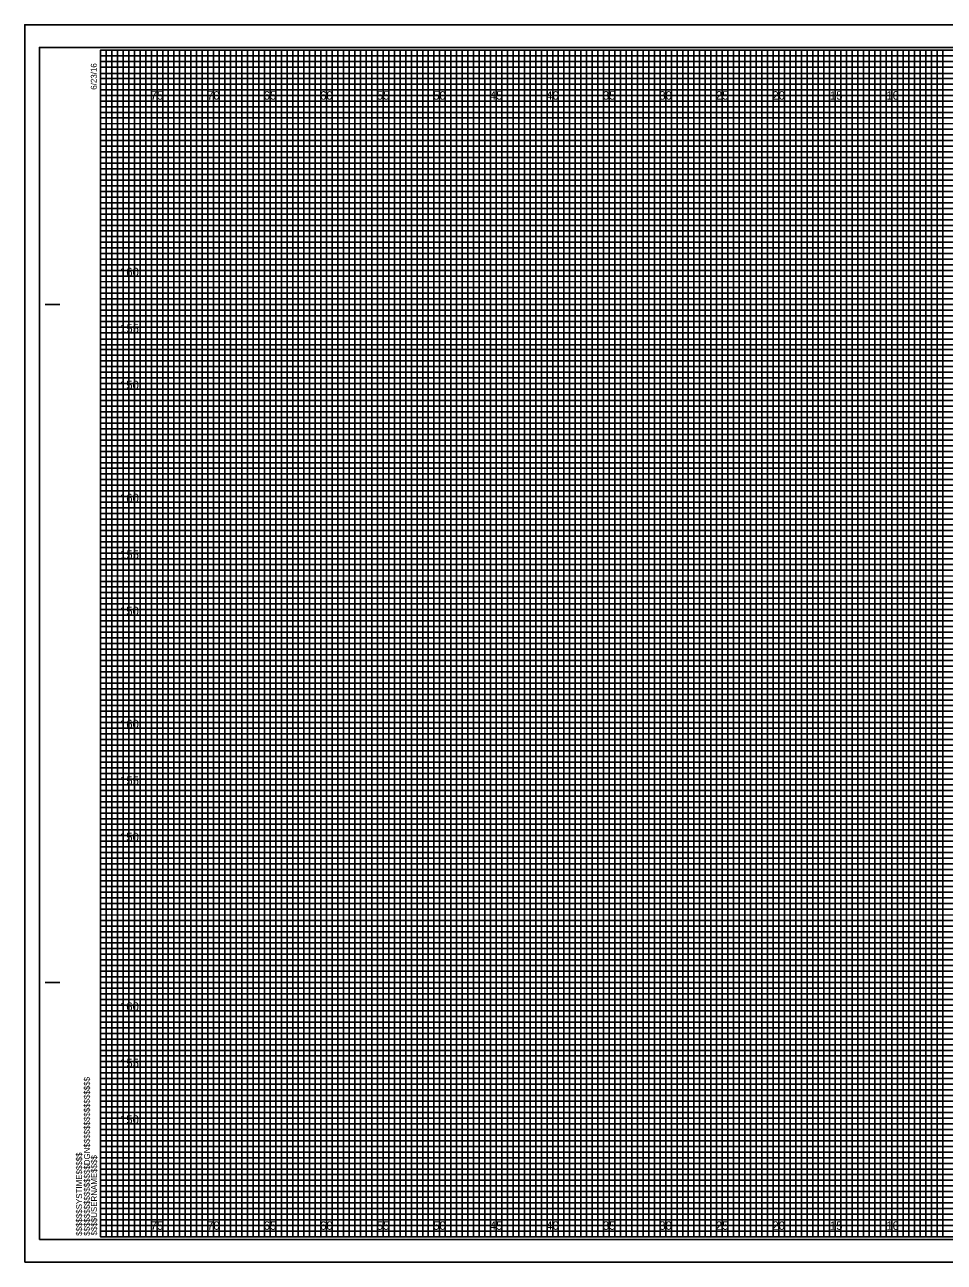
# Model space of a CAD drawing. Extents: x -7 to 162, y 108 to 217.
# Drawn here: x -6.7 to 74.6, y 107.7 to 217.2 of the extents above; entities that cross this region are included whole.
import ezdxf

# ---------------------------------------------------------------- set-up
doc = ezdxf.new("R2010")
doc.units = 0
for name, color, linetype in [('Prop CMT Shear Line', 7, 'Continuous'), ('Prop XS Earthwork Shape', 7, 'Continuous'), ('Prop XS Elevation Labels', 7, 'Continuous'), ('Scratch_Level_1', 7, 'Continuous'), ('Sheet Cross Section CELL', 7, 'Continuous'), ('Sheet Cross Section Grid Minor 1 CELL', 7, 'Continuous'), ('Sheet Cross Section Grid Minor 2 CELL', 7, 'Continuous'), ('Sheet Cutting Line CELL', 7, 'Continuous'), ('Sheet DOT Grid CELL', 7, 'Continuous'), ('Sheet Plot Border Inside CELL', 7, 'Continuous'), ('Sheet Plot Border Outside CELL', 7, 'Continuous')]:
    doc.layers.add(name, color=color, linetype=linetype)

msp = doc.modelspace()

# ---------------------------------------------------------------- linework, layer by layer
at = {"layer": 'Prop CMT Shear Line'}
for p, q in [((5, 215), (0, 215)), ((5, 110), (5, 215)), ((15, 215), (10, 215)), ((10, 215), (10, 110)), ((15, 110), (15, 215)), ((25, 215), (20, 215)), ((20, 215), (20, 110)), ((25, 110), (25, 215)), ((35, 215), (30, 215)), ((30, 215), (30, 110)), ((35, 110), (35, 215)), ((45, 215), (40, 215)), ((40, 215), (40, 110)), ((45, 110), (45, 215)), ((55, 215), (50, 215)), ((50, 215), (50, 110)), ((55, 110), (55, 215)), ((65, 215), (60, 215)), ((60, 215), (60, 110)), ((65, 110), (65, 215)), ((75, 215), (70, 215)), ((70, 215), (70, 110)), ((10, 110), (5, 110)), ((20, 110), (15, 110)), ((30, 110), (25, 110)), ((40, 110), (35, 110)), ((50, 110), (45, 110)), ((60, 110), (55, 110)), ((70, 110), (65, 110))]:
    msp.add_line(p, q, dxfattribs=at)
for points in [[(0, 210), (160, 210), (160, 205), (0, 205)], [(0, 200), (160, 200), (160, 195), (0, 195)], [(0, 190), (160, 190), (160, 185), (0, 185)], [(0, 180), (160, 180), (160, 175), (0, 175)], [(0, 170), (160, 170), (160, 165), (0, 165)], [(0, 160), (160, 160), (160, 155), (0, 155)], [(0, 150), (160, 150), (160, 145), (0, 145)], [(0, 140), (160, 140), (160, 135), (0, 135)], [(0, 130), (160, 130), (160, 125), (0, 125)], [(0, 120), (160, 120), (160, 115), (0, 115)]]:
    msp.add_lwpolyline(points, dxfattribs=at)
at = {"layer": 'Prop XS Earthwork Shape'}
for points in [[(0, 215), (2.5, 215), (2.5, 110), (7.5, 110), (7.5, 215), (12.5, 215), (12.5, 110), (17.5, 110), (17.5, 215), (22.5, 215), (22.5, 110), (27.5, 110), (27.5, 215), (32.5, 215), (32.5, 110), (37.5, 110), (37.5, 215), (42.5, 215), (42.5, 110), (47.5, 110), (47.5, 215), (52.5, 215), (52.5, 110), (57.5, 110), (57.5, 215), (62.5, 215), (62.5, 110), (67.5, 110), (67.5, 215), (72.5, 215), (72.5, 110), (77.5, 110)], [(0, 212.5), (137.5, 212.5)], [(0, 202.5), (160, 202.5), (160, 207.5), (0, 207.5)], [(0, 192.5), (160, 192.5), (160, 197.5), (0, 197.5)], [(0, 182.5), (160, 182.5), (160, 187.5), (0, 187.5)], [(0, 172.5), (160, 172.5), (160, 177.5), (0, 177.5)], [(0, 162.5), (160, 162.5), (160, 167.5), (0, 167.5)], [(0, 152.5), (160, 152.5), (160, 157.5), (0, 157.5)], [(0, 142.5), (160, 142.5), (160, 147.5), (0, 147.5)], [(0, 132.5), (160, 132.5), (160, 137.5), (0, 137.5)], [(0, 122.5), (160, 122.5), (160, 127.5), (0, 127.5)], [(0, 112.5), (160, 112.5), (160, 117.5), (0, 117.5)]]:
    msp.add_lwpolyline(points, dxfattribs=at)
at = {"layer": 'Sheet Cross Section CELL'}
for p, q in [((-4.9, 192.5), (-3.65, 192.5)), ((-4.85, 192.5), (-3.6, 192.5)), ((-4.9, 132.5), (-3.65, 132.5)), ((-4.85, 132.5), (-3.6, 132.5)), ((0, 110), (0, 110)), ((0, 110), (0, 110)), ((0, 110), (0, 110)), ((0, 110), (0, 110)), ((0, 110), (0, 110)), ((0, 110), (0, 110)), ((0, 110), (0, 110))]:
    msp.add_line(p, q, dxfattribs=at)
msp.add_lwpolyline([(160, 215), (0, 215), (0, 110), (160, 110)], close=True, dxfattribs=at)
at = {"layer": 'Sheet Cross Section Grid Minor 1 CELL'}
for p, q in [((0, 214.5), (130, 214.5)), ((130, 213.99), (0, 213.99)), ((0, 213.99), (0, 213.5)), ((0, 213.5), (130, 213.5)), ((130, 212.94), (0, 212.94)), ((0, 212.94), (0, 212)), ((0, 212), (160, 212))]:
    msp.add_line(p, q, dxfattribs=at)
for points in [[(0, 211.5), (135, 211.5), (160, 211.5), (160, 211), (0, 211)], [(0, 210.5), (160, 210.5), (160, 209.5), (0, 209.5)], [(0, 209), (160, 209), (160, 208.5), (0, 208.49)], [(0, 208), (160, 208), (160, 207), (0, 207)], [(0, 206.5), (160, 206.5), (160, 206), (0, 206)], [(0, 205.5), (160, 205.5), (160, 204.5), (0, 204.5)], [(0, 204), (160, 204), (160, 203.5), (0, 203.5)], [(0, 203), (160, 203), (160, 202), (0, 202)], [(0, 201.5), (160, 201.5), (160, 201), (0, 201)], [(0, 200.5), (160, 200.5), (160, 199.5), (0, 199.5)], [(0, 199), (160, 199), (160, 198.5), (0, 198.5)], [(0, 198), (160, 198), (160, 196.97), (160, 196.5), (160, 196), (0, 196)], [(0, 197), (160, 197), (160, 196.5), (0, 196.5)], [(0, 195.5), (160, 195.5), (160, 194.5), (0, 194.52)], [(0, 194.52), (160, 194.5), (160, 194), (0, 194)], [(0, 193.5), (160, 193.5), (160, 193), (0, 193)], [(0, 192), (160, 192), (160, 191.5), (0, 191.5)], [(0, 191), (160, 191), (160, 190.5), (0, 190.5)], [(-0.04, 189.44), (160, 189.44), (160, 188.94), (-0.04, 188.94)], [(0, 188.5), (160, 188.5), (160, 188), (0, 188)], [(0, 187), (160, 187), (160, 186.5), (0, 186.5)], [(0, 186), (160, 186), (160, 185.5), (0, 185.5)], [(0, 184.5), (160, 184.5), (160, 184), (0, 184)], [(0, 183.5), (160, 183.5), (160, 183), (0, 183)], [(0, 182), (160, 182), (160, 181.5), (0, 181.5)], [(0, 181), (160, 181), (160, 180.5), (0, 180.5)], [(0, 179.5), (160, 179.5), (160, 178.99), (0, 179)], [(0, 178.5), (160, 178.5), (160, 178), (0, 178)], [(0, 177), (160, 177), (160, 176.5), (0, 176.5)], [(0, 176), (160, 176), (160, 175.5), (0, 175.5)], [(0, 174.5), (160, 174.5), (160, 174), (0, 174)], [(0, 173.5), (160, 173.5), (160, 173), (0, 173)], [(0, 172), (160, 172), (160, 171.5), (0, 171.5)], [(0, 171), (160, 171), (160, 170.5), (0, 170.5)], [(0, 169.5), (160, 169.5), (160, 169), (0, 169)], [(0, 168.5), (160.03, 168.46), (160, 168), (0, 168)], [(0, 167), (160, 167), (160, 166.5), (0, 166.5)], [(0, 166), (160, 166), (160, 165.5), (0, 165.5)], [(0, 164.5), (160, 164.5), (160, 164), (0, 164)], [(0, 163.5), (160, 163.5), (160, 163), (0, 163)], [(0, 162), (160, 162), (160, 161.5), (0, 161.5)], [(0, 161), (160, 161), (160, 160.5), (0, 160.5)], [(0, 159.5), (160, 159.5), (160, 159), (0, 159)], [(0, 158.5), (160, 158.5), (160, 158), (0, 158)], [(0, 157), (160, 157), (160, 156.5), (0, 156.5)], [(0, 156), (160, 156), (160, 155.5), (0, 155.5)], [(0, 154.5), (160, 154.5), (160, 154), (0, 154)], [(0, 153.5), (160, 153.5), (160, 153), (0, 153)], [(0, 152), (160, 152), (160, 151.5), (0, 151.5)], [(0, 151), (160, 151), (160, 150.5), (0, 150.5)], [(0, 149.5), (160, 149.5), (160, 148.99), (0, 149)], [(0, 148.5), (160, 148.5), (160, 148), (0, 148)], [(0, 147), (160, 147), (160, 146.5), (0, 146.5)], [(0, 146), (160, 146), (160, 145.5), (0, 145.5)], [(0, 144.5), (160, 144.5), (160, 144), (0, 144)], [(0, 143.5), (160, 143.5), (160, 143), (0, 143)], [(0, 142), (160, 142), (160, 141.5), (0, 141.5)], [(0, 141), (160, 141), (160, 140.5), (0, 140.5)], [(0, 139.5), (160, 139.5), (160, 139), (0, 139)], [(0, 138.5), (160.03, 138.46), (160, 138), (0, 138)], [(0, 137), (160, 137), (160, 136.5), (0, 136.5)], [(0, 136), (160, 136), (160, 135.5), (0, 135.5)], [(0, 134.5), (160, 134.5), (160, 134), (0, 134)], [(0, 133.5), (160, 133.5), (160, 133), (0, 133)], [(0, 132), (160, 132), (160, 131.5), (0, 131.5)], [(0, 131), (160, 131), (160, 130.5), (0, 130.5)], [(0, 129.5), (160, 129.5), (160, 129), (0, 129)], [(0, 128.5), (160, 128.5), (160, 128), (0, 128)], [(0, 127), (160, 127), (160, 126.5), (0, 126.5)], [(0, 126), (160, 126), (160, 125.5), (0, 125.5)], [(0, 124.5), (160, 124.5), (160, 124), (0, 124)], [(0, 123.5), (160, 123.5), (160, 123), (0, 123)], [(0, 122), (160, 122), (160, 121.5), (0, 121.5)], [(0, 121), (160, 121), (160, 120.5), (0, 120.5)], [(0, 119.5), (160, 119.5), (160, 119), (0, 119)], [(0, 118.5), (160, 118.5), (160, 118), (0, 118)], [(0, 117), (160, 117), (160, 116.5), (0, 116.5)], [(0, 116), (160, 116), (160, 115.5), (0, 115.5)], [(0, 114.5), (160, 114.5), (160, 114), (0, 114)], [(0, 113.5), (160, 113.5), (160, 113), (0, 113)], [(0, 112), (160, 112), (160, 111.5), (0, 111.5)], [(0, 111), (160, 111), (160, 110.5), (0, 110.5)]]:
    msp.add_lwpolyline(points, dxfattribs=at)
at = {"layer": 'Sheet Cross Section Grid Minor 2 CELL'}
for points in [[(0, 110), (0.5, 110), (0.5, 215), (1, 215), (1, 110)], [(1, 110), (1.5, 110), (1.5, 215), (2, 215), (2, 110)], [(2.5, 110), (3, 110), (3, 215), (3.5, 215), (3.5, 110)], [(3.5, 110), (4, 110), (4, 215), (4.5, 215), (4.5, 110)], [(5, 110), (5.5, 110), (5.5, 215), (6, 215), (6, 110)], [(6, 110), (6.5, 110), (6.5, 215), (7, 215), (7, 110)], [(7.5, 110), (8, 110), (8, 215), (8.5, 215), (8.5, 110)], [(8.5, 110), (9, 110), (9, 215), (9.5, 215), (9.5, 110)], [(10, 110), (10.5, 110), (10.5, 215), (11, 215), (11, 110)], [(11, 110), (11.5, 110), (11.5, 215), (12, 215), (12, 110)], [(12.5, 110), (13, 110), (13, 215), (13.5, 215), (13.5, 110)], [(13.5, 110), (14, 110), (14, 215), (14.5, 215), (14.5, 110)], [(15, 110), (15.5, 110), (15.5, 215), (16, 215), (16, 110)], [(16, 110), (16.5, 110), (16.5, 215), (17, 215), (17, 110)], [(17.5, 110), (18, 110), (18, 215), (18.5, 215), (18.5, 110)], [(18.5, 110), (19, 110), (19, 215), (19.5, 215), (19.5, 110)], [(20, 110), (20.5, 110), (20.5, 215), (21, 215), (21, 110)], [(21, 110), (21.5, 110), (21.5, 215), (22, 215), (22, 110)], [(22.5, 110), (23, 110), (23, 215), (23.5, 215), (23.5, 110)], [(23.5, 110), (24, 110), (24, 215), (24.5, 215), (24.5, 110)], [(25, 110), (25.5, 110), (25.5, 215), (26, 215), (26, 110)], [(26, 110), (26.5, 110), (26.5, 215), (27, 215), (27, 110)], [(27.5, 110), (28, 110), (28, 215), (28.5, 215), (28.5, 110)], [(28.5, 110), (29, 110), (29, 215), (29.5, 215), (29.5, 110)], [(30, 110), (30.5, 110), (30.5, 215), (31, 215), (31, 110)], [(31, 110), (31.5, 110), (31.5, 215), (32, 215), (32, 110)], [(32.5, 110), (33, 110), (33, 215), (33.5, 215), (33.5, 110)], [(33.5, 110), (34, 110), (34, 215), (34.5, 215), (34.5, 110)], [(35, 110), (35.5, 110), (35.5, 215), (36, 215), (36, 110)], [(36, 110), (36.5, 110), (36.5, 215), (37, 215), (37, 110)], [(37.5, 110), (38, 110), (38, 215), (38.5, 215), (38.5, 110)], [(38.5, 110), (39, 110), (39, 215), (39.5, 215), (39.5, 110)], [(40, 110), (40.5, 110), (40.5, 215), (41, 215), (41, 110)], [(41, 110), (41.5, 110), (41.5, 215), (42, 215), (42, 110)], [(42.5, 110), (43, 110), (43, 215), (43.5, 215), (43.5, 110)], [(43.5, 110), (44, 110), (44, 215), (44.5, 215), (44.5, 110)], [(45, 110), (45.5, 110), (45.5, 215), (46, 215), (46, 110)], [(46, 110), (46.5, 110), (46.5, 215), (47, 215), (47, 110)], [(47.5, 110), (48, 110), (48, 215), (48.5, 215), (48.5, 110)], [(48.5, 110), (49, 110), (49, 215), (49.5, 215), (49.5, 110)], [(50, 110), (50.5, 110), (50.5, 215), (51, 215), (51, 110)], [(51, 110), (51.5, 110), (51.5, 215), (52, 215), (52, 110)], [(52.5, 110), (53, 110), (53, 215), (53.5, 215), (53.5, 110)], [(53.5, 110), (54, 110), (54, 215), (54.5, 215), (54.5, 110)], [(55, 110), (55.5, 110), (55.5, 215), (56, 215), (56, 110)], [(56, 110), (56.5, 110), (56.5, 215), (57, 215), (57, 110)], [(57.5, 110), (58, 110), (58, 215), (58.5, 215), (58.5, 110)], [(58.5, 110), (59, 110), (59, 215), (59.5, 215), (59.5, 110)], [(60, 110), (60.5, 110), (60.5, 215), (61, 215), (61, 110)], [(61, 110), (61.5, 110), (61.5, 215), (62, 215), (62, 110)], [(62.5, 110), (63, 110), (63, 215), (63.5, 215), (63.5, 110)], [(63.5, 110), (64, 110), (64, 215), (64.5, 215), (64.5, 110)], [(65, 110), (65.5, 110), (65.5, 215), (66, 215), (66, 110)], [(66, 110), (66.5, 110), (66.5, 215), (67, 215), (67, 110)], [(67.5, 110), (68, 110), (68, 215), (68.5, 215), (68.5, 110)], [(68.5, 110), (69, 110), (69, 215), (69.5, 215), (69.5, 110)], [(70, 110), (70.5, 110), (70.5, 215), (71, 215), (71, 110)], [(71, 110), (71.5, 110), (71.5, 215), (72, 215), (72, 110)], [(72.5, 110), (73, 110), (73, 215), (73.5, 215), (73.5, 110)], [(73.5, 110), (74, 110), (74, 215), (74.5, 215), (74.5, 110)]]:
    msp.add_lwpolyline(points, dxfattribs=at)
at = {"layer": 'Sheet Cutting Line CELL'}
for p, q in [((161.65, 217.25), (-6.7, 217.25)), ((-6.7, 217.25), (-6.7, 107.75)), ((-6.7, 107.75), (161.65, 107.75))]:
    msp.add_line(p, q, dxfattribs=at)
at = {"layer": 'Sheet DOT Grid CELL'}
for p, q in [((5, 110), (5, 215)), ((10, 110), (10, 215)), ((15, 110), (15, 215)), ((20, 110), (20, 215)), ((25, 110), (25, 215)), ((30, 110), (30, 215)), ((35, 110), (35, 215)), ((40, 110), (40, 215)), ((45, 110), (45, 215)), ((50, 110), (50, 215)), ((55, 110), (55, 215)), ((60, 110), (60, 215)), ((65, 110), (65, 215)), ((70, 110), (70, 215)), ((0, 210), (160, 210)), ((0, 205), (160, 205)), ((0, 200), (160, 200)), ((0, 195), (160, 195)), ((0, 190), (160, 190)), ((0, 185), (160, 185)), ((0, 180), (160, 180)), ((0, 175), (160, 175)), ((0, 170), (160, 170)), ((0, 165), (160, 165)), ((0, 160), (160, 160)), ((0, 155), (160, 155)), ((0, 150), (160, 150)), ((0, 145), (160, 145)), ((0, 140), (160, 140)), ((0, 135), (160, 135)), ((0, 130), (160, 130)), ((0, 125), (160, 125)), ((0, 120), (160, 120)), ((0, 115), (160, 115))]:
    msp.add_line(p, q, dxfattribs=at)
at = {"layer": 'Sheet Plot Border Inside CELL'}
msp.add_lwpolyline([(-5.4, 109.75), (161.2, 109.75), (161.2, 215.25), (-5.4, 215.25)], close=True, dxfattribs=at)
at = {"layer": 'Sheet Plot Border Outside CELL'}
msp.add_lwpolyline([(-6.7, 107.75), (161.65, 107.75), (161.65, 217.25), (-6.7, 217.25)], close=True, dxfattribs=at)

# ---------------------------------------------------------------- texts
at = {"layer": 'Prop XS Elevation Labels'}
for s, p in [('160', (1.72, 195)), ('155', (1.73, 190)), ('150', (1.72, 185)), ('160', (1.72, 175)), ('155', (1.73, 170)), ('150', (1.72, 165)), ('160', (1.72, 155)), ('155', (1.73, 150)), ('150', (1.72, 145)), ('160', (1.72, 130)), ('155', (1.73, 125)), ('150', (1.72, 120))]:
    msp.add_text(s, height=0.75, dxfattribs=at).set_placement(p)
at = {"layer": 'Scratch_Level_1'}
for s, p in [('75', (4.44, 210.62)), ('70', (9.43, 210.62)), ('65', (14.44, 210.62)), ('60', (19.43, 210.62)), ('55', (24.44, 210.62)), ('50', (29.43, 210.62)), ('45', (34.44, 210.62)), ('40', (39.43, 210.62)), ('35', (44.44, 210.62)), ('30', (49.43, 210.62)), ('25', (54.44, 210.62)), ('20', (59.43, 210.62)), ('15', (64.53, 210.62)), ('10', (69.52, 210.62)), ('75', (4.44, 110.62)), ('70', (9.43, 110.62)), ('65', (14.44, 110.62)), ('60', (19.43, 110.62)), ('55', (24.44, 110.62)), ('50', (29.43, 110.62)), ('45', (34.44, 110.62)), ('40', (39.43, 110.62)), ('35', (44.44, 110.62)), ('30', (49.43, 110.62)), ('25', (54.44, 110.62)), ('20', (59.43, 110.62)), ('15', (64.53, 110.62)), ('10', (69.52, 110.62))]:
    msp.add_text(s, height=0.75, dxfattribs=at).set_placement(p)
at = {"layer": 'Sheet Cross Section CELL'}
for s, p in [('6/23/16', (-0.33, 211.5)), ('$$$$$$$$$$$$$$$$DGN$$$$$$$$$$$$$$$$', (-0.94, 110.09)), ('$$$$$$SYSTIME$$$$$', (-1.63, 110.09)), ('$$$$USERNAME$$$$', (-0.31, 110.12))]:
    msp.add_text(s, height=0.525, rotation=90, dxfattribs=at).set_placement(p)

doc.saveas('drawing.dxf')
